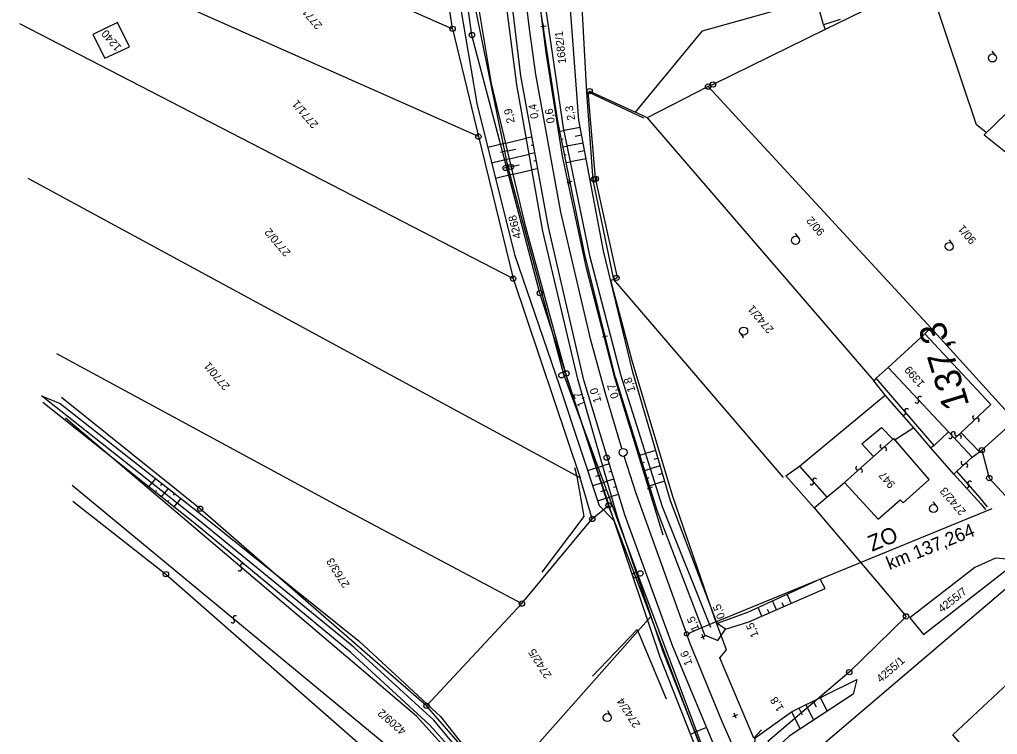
# Model space of a CAD drawing. Extents: x -658910 to -658078, y -1170373 to -1169331.
# Drawn here: x -658513.9 to -658330.6, y -1170257.1 to -1170123.2 of the extents above; entities that cross this region are included whole.
import ezdxf

# ---------------------------------------------------------------- set-up
doc = ezdxf.new("R2010")
doc.units = 0
for name, color, linetype in [('Vrstva 1', 7, 'Continuous'), ('Vrstva 10', 7, 'Continuous'), ('Vrstva 11', 7, 'Continuous'), ('Vrstva 12', 7, 'Continuous'), ('Vrstva 14', 7, 'Continuous'), ('Vrstva 26', 7, 'Continuous'), ('Vrstva 38', 7, 'Continuous'), ('Vrstva 39', 7, 'Continuous'), ('Vrstva 6', 7, 'Continuous'), ('Vrstva 7', 7, 'Continuous'), ('Vrstva 8', 7, 'Continuous'), ('Vrstva 9', 7, 'Continuous')]:
    doc.layers.add(name, color=color, linetype=linetype)

msp = doc.modelspace()

# ---------------------------------------------------------------- linework, layer by layer
at = {"layer": 'Vrstva 1'}
for p, q in [((-658429.152, -1170126.129), (-658429.052, -1170126.129)), ((-658407.12, -1170136.629), (-658407.02, -1170136.629)), ((-658406.295, -1170153.163), (-658406.195, -1170153.163)), ((-658406.295, -1170153.163), (-658406.195, -1170153.163)), ((-658405.941, -1170153.051), (-658405.841, -1170153.051)), ((-658402.07, -1170171.6), (-658401.97, -1170171.6)), ((-658416.448, -1170174.469), (-658416.348, -1170174.469)), ((-658403.55, -1170214.23), (-658403.45, -1170214.23)), ((-658403.55, -1170214.23), (-658403.45, -1170214.23)), ((-658347.82, -1170235.02), (-658347.72, -1170235.02)), ((-658358.46, -1170245.469), (-658358.36, -1170245.469))]:
    msp.add_line(p, q, dxfattribs=at)
for points in [[(-658403.5, -1170214.23), (-658416.398, -1170174.469), (-658429.102, -1170126.129), (-658434.469, -1170087.609), (-658436.09, -1170052.059), (-658435.91, -1170014.719), (-658434.91, -1170000.301)], [(-658407.281, -1170000.499), (-658408.153, -1170029.241), (-658409.34, -1170063.27), (-658409.781, -1170095.35), (-658409.699, -1170099.11), (-658407.621, -1170136.909), (-658406.442, -1170153.331), (-658402.571, -1170171.88), (-658370.821, -1170208.971)], [(-658370.27, -1170208.691), (-658365.012, -1170214.699), (-658352.621, -1170229.211), (-658347.77, -1170235.02), (-658358.41, -1170245.469), (-658373.641, -1170258.449), (-658367.441, -1170262.461), (-658359.102, -1170278.891), (-658351.488, -1170290.83), (-658344.789, -1170302.82), (-658321.379, -1170329.199), (-658330.469, -1170332.85)], [(-658330.469, -1170332.85), (-658356.398, -1170343.289), (-658366.66, -1170318.129), (-658369.211, -1170312.75), (-658376.602, -1170296.77), (-658379.789, -1170292.191), (-658390.738, -1170282.121), (-658389.18, -1170276.711), (-658384.27, -1170264.699), (-658395.621, -1170235.01), (-658403.5, -1170214.23)]]:
    msp.add_lwpolyline(points, dxfattribs=at)
for centre in [(-658429.102, -1170126.129), (-658407.07, -1170136.629), (-658406.245, -1170153.163), (-658406.245, -1170153.163), (-658405.891, -1170153.051), (-658402.02, -1170171.6), (-658416.398, -1170174.469), (-658403.5, -1170214.23), (-658403.5, -1170214.23), (-658347.77, -1170235.02), (-658358.41, -1170245.469)]:
    msp.add_circle(centre, 0.499, dxfattribs=at)
at = {"layer": 'Vrstva 10'}
for points in [[(-658398.979, -1170189.297), (-658404.442, -1170166.563), (-658409.088, -1170142.051), (-658411.131, -1170114.565), (-658412.045, -1170080.658), (-658411.524, -1170049.223), (-658409, -1170012.742), (-658406.097, -1169985.499), (-658398.397, -1169958.238), (-658397.23, -1169955.206)], [(-658417.872, -1169961.611), (-658420.49, -1169976.06), (-658420.7, -1169976.84), (-658423.094, -1169993.471), (-658426.642, -1170037.568), (-658427.061, -1170074.546), (-658424.838, -1170104.223), (-658420.758, -1170135.42), (-658415.909, -1170162.863), (-658409.329, -1170190.564)], [(-658402.315, -1170190.348), (-658407.653, -1170169.771), (-658412.172, -1170148.826), (-658415.215, -1170129.375), (-658417.727, -1170109.679), (-658419.363, -1170090.792), (-658420.432, -1170070.237), (-658420.644, -1170050.611), (-658420.516, -1170040.788), (-658419.395, -1170021.018), (-658418.485, -1170009.912), (-658416.352, -1169990.562), (-658415.125, -1169981.811), (-658411.561, -1169961.716)], [(-658411.065, -1170191.125), (-658419.009, -1170162.093), (-658425.437, -1170135.194), (-658430.311, -1170105.886), (-658434.217, -1170075.522), (-658434.962, -1170038.771), (-658431.942, -1169996.387), (-658433.406, -1169990.734), (-658432.798, -1169972.528), (-658431.022, -1169965.688)], [(-658408.116, -1170190.76), (-658414.795, -1170162.084), (-658419.971, -1170133.751), (-658423.753, -1170102.123), (-658425.468, -1170076.574), (-658425.385, -1170038.217), (-658422.281, -1169996.311), (-658419.933, -1169977.592), (-658415.95, -1169967.863)], [(-658434.217, -1170075.522), (-658435.579, -1170036.672), (-658434.69, -1170005.528), (-658435.667, -1169999.009), (-658437.119, -1170012.108), (-658437.881, -1170041.388), (-658436.997, -1170074.409), (-658433.517, -1170107.658), (-658428.206, -1170138.963), (-658421.128, -1170167.236), (-658412.684, -1170191.854)], [(-658402.19, -1170190.341), (-658407.996, -1170166.975), (-658412.991, -1170142.221), (-658416.888, -1170117.058), (-658418.194, -1170104.631), (-658416.97, -1170109.116), (-658415.845, -1170117.564), (-658412.003, -1170143.514), (-658407.102, -1170167.433), (-658401.285, -1170189.676)], [(-658412.605, -1170144.132), (-658411.906, -1170143.991)], [(-658408.831, -1170143.407), (-658411.906, -1170143.99)], [(-658422.766, -1170146.37), (-658426.149, -1170147.178)], [(-658422.766, -1170146.37), (-658418.922, -1170145.451)], [(-658417.868, -1170145.258), (-658418.922, -1170145.451)], [(-658412.309, -1170145.602), (-658412.027, -1170145.545)], [(-658408.272, -1170146.355), (-658411.303, -1170146.929)], [(-658408.552, -1170144.881), (-658409.773, -1170145.113)], [(-658422.417, -1170147.829), (-658423.764, -1170148.15)], [(-658422.417, -1170147.829), (-658420.915, -1170147.469)], [(-658417.329, -1170148.209), (-658418.4, -1170148.405)], [(-658417.599, -1170146.734), (-658418.024, -1170146.812)], [(-658412.012, -1170147.073), (-658411.303, -1170146.93)], [(-658407.993, -1170147.829), (-658409.197, -1170148.057)], [(-658422.069, -1170149.288), (-658425.421, -1170150.089)], [(-658422.069, -1170149.288), (-658418.399, -1170148.41)], [(-658417.06, -1170149.685), (-658417.491, -1170149.764)], [(-658411.715, -1170148.543), (-658411.43, -1170148.485)], [(-658411.419, -1170150.013), (-658410.701, -1170149.869)], [(-658407.714, -1170149.303), (-658410.701, -1170149.869)], [(-658421.72, -1170150.747), (-658423.055, -1170151.065)], [(-658421.72, -1170150.747), (-658420.287, -1170150.404)], [(-658421.372, -1170152.205), (-658417.876, -1170151.37)], [(-658416.79, -1170151.161), (-658417.878, -1170151.359)], [(-658421.372, -1170152.206), (-658424.692, -1170152.999)], [(-658393.284, -1170219.793), (-658402.315, -1170190.348)], [(-658402.19, -1170190.341), (-658394.439, -1170215.11), (-658385.518, -1170238.461), (-658383.011, -1170239.51), (-658381.573, -1170237.386), (-658383.18, -1170236.346), (-658391.879, -1170213.374), (-658398.979, -1170189.297)], [(-658401.285, -1170189.676), (-658393.487, -1170214.462), (-658384.399, -1170237.018)], [(-658412.684, -1170191.854), (-658405.295, -1170214.249), (-658402.529, -1170217.03)], [(-658411.065, -1170191.125), (-658402.529, -1170217.03), (-658393.894, -1170242.581), (-658385.65, -1170263.506), (-658396.929, -1170273.583), (-658403.806, -1170280.374), (-658404.2, -1170281.887), (-658401.638, -1170280.609), (-658395.562, -1170275.336), (-658385.028, -1170264.873), (-658381.412, -1170264.462)], [(-658385.028, -1170264.873), (-658384.852, -1170262.895), (-658393.339, -1170241.462), (-658401.853, -1170216.412), (-658409.267, -1170190.554)], [(-658382.68, -1170261.755), (-658391.453, -1170240.672), (-658400.481, -1170215.988), (-658408.116, -1170190.76)], [(-658427.834, -1170264.568), (-658436.224, -1170254.487), (-658451.234, -1170240.802), (-658480.159, -1170217.142), (-658509.779, -1170193.688), (-658506.26, -1170195.157), (-658479.671, -1170216.029), (-658450.164, -1170239.717), (-658435.016, -1170253.798), (-658426.918, -1170264.043), (-658428.464, -1170264.929), (-658436.985, -1170255.369), (-658451.79, -1170241.804), (-658480.719, -1170217.852), (-658509.548, -1170194.956)], [(-658397.652, -1170204.843), (-658396.615, -1170204.519)], [(-658394.66, -1170203.941), (-658396.615, -1170204.518)], [(-658405.77, -1170207.193), (-658404.606, -1170206.81)], [(-658403.371, -1170206.44), (-658404.605, -1170206.813)], [(-658397.204, -1170206.275), (-658396.788, -1170206.145)], [(-658393.812, -1170206.819), (-658395.715, -1170207.38)], [(-658394.236, -1170205.38), (-658395.008, -1170205.607)], [(-658405.771, -1170207.193), (-658407.441, -1170207.744)], [(-658405.301, -1170208.618), (-658405.969, -1170208.838)], [(-658405.301, -1170208.618), (-658404.857, -1170208.472)], [(-658402.936, -1170207.875), (-658403.438, -1170208.028)], [(-658396.756, -1170207.707), (-658395.715, -1170207.38)], [(-658393.387, -1170208.257), (-658394.138, -1170208.479)], [(-658489.628, -1170210.776), (-658489.076, -1170210.081)], [(-658488.379, -1170209.193), (-658489.076, -1170210.081)], [(-658487.2, -1170210.119), (-658487.48, -1170210.476)], [(-658404.832, -1170210.042), (-658406.501, -1170210.592)], [(-658404.832, -1170210.042), (-658403.778, -1170209.695)], [(-658402.501, -1170209.312), (-658403.778, -1170209.698)], [(-658396.308, -1170209.138), (-658395.891, -1170209.007)], [(-658395.86, -1170210.569), (-658394.814, -1170210.242)], [(-658392.963, -1170209.696), (-658394.814, -1170210.242)], [(-658488.454, -1170211.709), (-658488.232, -1170211.43)], [(-658487.279, -1170212.642), (-658486.724, -1170211.943)], [(-658486.02, -1170211.045), (-658486.724, -1170211.943)], [(-658484.84, -1170211.972), (-658485.123, -1170212.333)], [(-658404.362, -1170211.467), (-658405.03, -1170211.687)], [(-658404.362, -1170211.467), (-658403.963, -1170211.336)], [(-658401.632, -1170212.183), (-658402.951, -1170212.582)], [(-658402.067, -1170210.747), (-658402.586, -1170210.904)], [(-658486.104, -1170213.575), (-658485.882, -1170213.294)], [(-658484.93, -1170214.507), (-658484.372, -1170213.805)], [(-658483.66, -1170212.897), (-658484.372, -1170213.805)], [(-658403.893, -1170212.892), (-658405.561, -1170213.441)], [(-658403.893, -1170212.892), (-658402.951, -1170212.582)], [(-658381.573, -1170237.386), (-658377.211, -1170236.054), (-658362.918, -1170229.77), (-658363.874, -1170228.032), (-658377.506, -1170234.284), (-658383.18, -1170236.346)], [(-658372.041, -1170233.781), (-658372.774, -1170232.114)], [(-658370.668, -1170233.177), (-658370.965, -1170232.501)], [(-658369.295, -1170232.573), (-658370.047, -1170230.863)], [(-658374.787, -1170234.988), (-658375.501, -1170233.365)], [(-658373.414, -1170234.384), (-658373.703, -1170233.726)], [(-658376.215, -1170261.644), (-658376.011, -1170257.794), (-658369.212, -1170252.874), (-658357.015, -1170246.85), (-658357.668, -1170249.617), (-658369.7, -1170257.467), (-658372.946, -1170260.508)], [(-658365.177, -1170250.881), (-658364.634, -1170251.981)], [(-658363.832, -1170250.217), (-658362.554, -1170252.805)], [(-658367.867, -1170252.209), (-658367.26, -1170253.438)], [(-658366.522, -1170251.545), (-658365.085, -1170254.456)], [(-658369.212, -1170252.874), (-658367.615, -1170256.107)], [(-658385.149, -1170255.822), (-658387.299, -1170256.716)], [(-658388.187, -1170257.067), (-658387.298, -1170256.717)]]:
    msp.add_lwpolyline(points, dxfattribs=at)
at = {"layer": 'Vrstva 12'}
for p, q in [((-658416.194, -1170124.502), (-658415.203, -1170124.361)), ((-658415.628, -1170124.927), (-658415.769, -1170123.936)), ((-658411.293, -1170153.71), (-658410.318, -1170153.487)), ((-658410.694, -1170154.086), (-658410.917, -1170153.111)), ((-658404.665, -1170182.66), (-658403.69, -1170182.437)), ((-658404.066, -1170183.036), (-658404.289, -1170182.061)), ((-658395.646, -1170211.469), (-658395.985, -1170210.528)), ((-658395.345, -1170210.829), (-658396.286, -1170211.168)), ((-658385.304, -1170238.687), (-658386.231, -1170239.062)), ((-658385.58, -1170239.338), (-658385.955, -1170238.411)), ((-658379.347, -1170253.435), (-658380.262, -1170253.838)), ((-658379.603, -1170254.094), (-658380.006, -1170253.179))]:
    msp.add_line(p, q, dxfattribs=at)
for points in [[(-658399.067, -1170187.176), (-658403.097, -1170172.101), (-658401.841, -1170171.547), (-658405.936, -1170152.959), (-658407.353, -1170136.782), (-658396.958, -1170141.634)], [(-658399.067, -1170187.176), (-658403.097, -1170172.101), (-658401.841, -1170171.547), (-658405.936, -1170152.959), (-658407.353, -1170136.782), (-658396.958, -1170141.634)], [(-658374.854, -1170256.244), (-658376.266, -1170257.857), (-658382.638, -1170242.795), (-658381.434, -1170241.263), (-658383.587, -1170235.421), (-658391.447, -1170212.589), (-658399.067, -1170187.176)], [(-658374.854, -1170256.244), (-658376.266, -1170257.857), (-658382.638, -1170242.795), (-658381.434, -1170241.263), (-658383.587, -1170235.421), (-658391.447, -1170212.589), (-658399.067, -1170187.176)], [(-658409.885, -1170207.127), (-658409.448, -1170208.785), (-658408.134, -1170216.333), (-658416.024, -1170226.737)], [(-658409.885, -1170207.127), (-658409.448, -1170208.785), (-658408.134, -1170216.333), (-658416.024, -1170226.737)], [(-658406.538, -1170246.188), (-658398.144, -1170237.495), (-658392.744, -1170250.489)], [(-658406.538, -1170246.188), (-658398.144, -1170237.495), (-658392.744, -1170250.489)]]:
    msp.add_lwpolyline(points, dxfattribs=at)
at = {"layer": 'Vrstva 14'}
msp.add_circle((-658403.86, -1170205.272), 0.5, dxfattribs=at)
at = {"layer": 'Vrstva 26'}
for points in [[(-658422.321, -1170150.908), (-658429.464, -1170116.165)], [(-658411.874, -1170189.684), (-658422.321, -1170150.908)], [(-658370.027, -1170300), (-658377.149, -1170282.049), (-658386.214, -1170258.657), (-658398.024, -1170227.132), (-658411.874, -1170189.684)]]:
    msp.add_lwpolyline(points, dxfattribs=at)
for centre in [(-658422.81, -1170151.008), (-658421.831, -1170150.807), (-658412.342, -1170189.857), (-658411.405, -1170189.51), (-658398.492, -1170227.307), (-658397.555, -1170226.956)]:
    msp.add_circle(centre, 0.5, dxfattribs=at)
at = {"layer": 'Vrstva 38'}
msp.add_lwpolyline([(-658388.616, -1170238.202), (-658386.485, -1170237.314), (-658331.614, -1170214.793)], dxfattribs=at)
msp.add_circle((-658388.892, -1170238.29), 0.4, dxfattribs=at)
at = {"layer": 'Vrstva 6'}
for points in [[(-658404.069, -1170193.255), (-658406.802, -1170183.303), (-658412.437, -1170159.296), (-658417.118, -1170133.524), (-658418.339, -1170124.958), (-658420.433, -1170107.363)], [(-658401, -1170203.584), (-658404.069, -1170193.255)], [(-658388.156, -1170240.29), (-658398.345, -1170211.986), (-658400.56, -1170205.015)], [(-658363.328, -1170296.271), (-658369.128, -1170283.84), (-658375.834, -1170269.208), (-658382.293, -1170254.576), (-658388.156, -1170240.29)]]:
    msp.add_lwpolyline(points, dxfattribs=at)
msp.add_circle((-658400.788, -1170204.296), 0.75, dxfattribs=at)
at = {"layer": 'Vrstva 8'}
for p, q in [((-658432.78, -1170124.961), (-658432.68, -1170124.961)), ((-658432.78, -1170124.961), (-658432.68, -1170124.961)), ((-658383.991, -1170135.379), (-658383.891, -1170135.379)), ((-658384.909, -1170135.77), (-658384.809, -1170135.77)), ((-658384.909, -1170135.77), (-658384.809, -1170135.77)), ((-658427.948, -1170145.15), (-658427.848, -1170145.15)), ((-658427.948, -1170145.15), (-658427.848, -1170145.15)), ((-658403, -1170155), (-658403, -1170155)), ((-658421.441, -1170171.75), (-658421.341, -1170171.75)), ((-658421.441, -1170171.75), (-658421.341, -1170171.75)), ((-658337.48, -1170200.6), (-658337.48, -1170200.6)), ((-658334.012, -1170204.199), (-658334.012, -1170204.199)), ((-658333.609, -1170203.879), (-658333.509, -1170203.879)), ((-658333.609, -1170203.879), (-658333.509, -1170203.879)), ((-658332.222, -1170209.1), (-658332.122, -1170209.1)), ((-658480.081, -1170214.85), (-658479.981, -1170214.85)), ((-658406.62, -1170216.76), (-658406.52, -1170216.76)), ((-658406.62, -1170216.76), (-658406.52, -1170216.76)), ((-658486.499, -1170227.109), (-658486.399, -1170227.109)), ((-658419.8, -1170232.629), (-658419.7, -1170232.629)), ((-658419.8, -1170232.629), (-658419.7, -1170232.629)), ((-658437.679, -1170251.781), (-658437.579, -1170251.781)), ((-658437.679, -1170251.781), (-658437.579, -1170251.781)), ((-658437.679, -1170251.781), (-658437.579, -1170251.781))]:
    msp.add_line(p, q, dxfattribs=at)
for points in [[(-658483.512, -1170102.52), (-658432.73, -1170124.961), (-658438.469, -1170085.941)], [(-658432.73, -1170124.961), (-658427.898, -1170145.15), (-658491.949, -1170116.66), (-658492.5, -1170116.51), (-658494.488, -1170117.301), (-658497.551, -1170107.359), (-658486.379, -1170104.051), (-658483.352, -1170113.789), (-658492.5, -1170116.51)], [(-658343.781, -1170115.711), (-658362.941, -1170125.1), (-658383.941, -1170135.379), (-658384.859, -1170135.77), (-658396.301, -1170141.629), (-658398.469, -1170140.59), (-658385.91, -1170125.309), (-658364.672, -1170119.32)], [(-658332.82, -1170144.281), (-658334.559, -1170142.949), (-658342.941, -1170117.961)], [(-658360.109, -1170123.199), (-658363.262, -1170124.211), (-658364.109, -1170121.039)], [(-658513.879, -1170123.961), (-658421.391, -1170171.75), (-658408.84, -1170209.09)], [(-658363.262, -1170124.211), (-658362.941, -1170125.1)], [(-658318.371, -1170130.531), (-658333.141, -1170144.789), (-658329.059, -1170148.059), (-658326.859, -1170149.789), (-658324.578, -1170151.859), (-658326, -1170153.76), (-658322.172, -1170156.539), (-658312.941, -1170163.66), (-658311.129, -1170161.539), (-658309.211, -1170162.891), (-658303.559, -1170155.359)], [(-658407.07, -1170136.629), (-658398.469, -1170140.59)], [(-658384.859, -1170135.77), (-658343.121, -1170180.961), (-658327.41, -1170198.301), (-658333.559, -1170203.879), (-658332.172, -1170209.1), (-658327.551, -1170214.141), (-658321.59, -1170219.16), (-658320.828, -1170219.93), (-658325.852, -1170225.359), (-658326.648, -1170224.5), (-658330.98, -1170224.109), (-658334.898, -1170225.871), (-658347.059, -1170235.289), (-658344.5, -1170238.391), (-658326.648, -1170224.5)], [(-658396.301, -1170141.629), (-658353.781, -1170190.871)], [(-658427.898, -1170145.15), (-658421.391, -1170171.75)], [(-658506.93, -1170185.75), (-658454.141, -1170214.391), (-658419.75, -1170232.629), (-658406.57, -1170216.76), (-658408.84, -1170209.09), (-658512.289, -1170153.02)], [(-658344.262, -1170182.09), (-658343.121, -1170180.961)], [(-658339.82, -1170200.449), (-658351.121, -1170188.41), (-658344.262, -1170182.09), (-658331.852, -1170195.35), (-658338.602, -1170201.67)], [(-658353.379, -1170190.391), (-658351.121, -1170188.41)], [(-658338.281, -1170207.83), (-658335.379, -1170205.191), (-658339.82, -1170200.449), (-658342.469, -1170203.031), (-658353.379, -1170190.391), (-658353.781, -1170190.871)], [(-658370.27, -1170208.691), (-658367.711, -1170206.859), (-658351.66, -1170193.57), (-658353.781, -1170190.871)], [(-658367.441, -1170262.461), (-658305.121, -1170209.41), (-658290.129, -1170191.49)], [(-658437.629, -1170251.781), (-658480.031, -1170214.85), (-658506.031, -1170194.039)], [(-658338.809, -1170208.371), (-658343.102, -1170203.461), (-658346.309, -1170199.711), (-658351.66, -1170193.57)], [(-658439.469, -1170253.74), (-658505.27, -1170197.9)], [(-658365.012, -1170214.699), (-658362.602, -1170212.67), (-658359.27, -1170209.91), (-658353.012, -1170216.809), (-658348.84, -1170213.211), (-658348.289, -1170213.74), (-658343.43, -1170209.35), (-658350.031, -1170201.67), (-658353.84, -1170205.07), (-658356.039, -1170202.691), (-658352.352, -1170199.609), (-658350.238, -1170201.809)], [(-658346.309, -1170199.711), (-658349.801, -1170201.949)], [(-658334.012, -1170204.199), (-658337.48, -1170200.6)], [(-658342.469, -1170203.031), (-658343.102, -1170203.461)], [(-658353.84, -1170205.07), (-658359.27, -1170209.91)], [(-658335.379, -1170205.191), (-658333.559, -1170203.879)], [(-658367.711, -1170206.859), (-658362.602, -1170212.67)], [(-658332.531, -1170214.466), (-658333.922, -1170212.77), (-658338.281, -1170207.83), (-658338.809, -1170208.371), (-658333.75, -1170213.941), (-658332.905, -1170215.021)], [(-658443.422, -1170260.6), (-658504.02, -1170210.5)], [(-658503.871, -1170213.42), (-658486.449, -1170227.109), (-658446.422, -1170262.219)], [(-658406.57, -1170216.76), (-658403.5, -1170214.23)], [(-658419.75, -1170232.629), (-658437.629, -1170251.781)], [(-658407.27, -1170321.32), (-658411.031, -1170302.51), (-658413.109, -1170292.49), (-658415.109, -1170286.801), (-658420.691, -1170271.91), (-658424.129, -1170267.281), (-658395.621, -1170235.01)], [(-658324.686, -1170273.482), (-658339.031, -1170257.199), (-658327.789, -1170246.691)], [(-658424.129, -1170267.281), (-658437.629, -1170251.781)], [(-658411.93, -1170371.551), (-658412.051, -1170358.6), (-658411.02, -1170322.441), (-658416.07, -1170292.65), (-658423.141, -1170271.82), (-658439.469, -1170253.74)]]:
    msp.add_lwpolyline(points, dxfattribs=at)
msp.add_lwpolyline([(-658497.93, -1170130.461), (-658493.25, -1170128.33), (-658495.551, -1170123.77), (-658500.172, -1170126.039)], close=True, dxfattribs=at)
for centre in [(-658432.73, -1170124.961), (-658432.73, -1170124.961), (-658384.859, -1170135.77), (-658384.859, -1170135.77), (-658383.941, -1170135.379), (-658427.898, -1170145.15), (-658427.898, -1170145.15), (-658421.391, -1170171.75), (-658421.391, -1170171.75), (-658333.559, -1170203.879), (-658333.559, -1170203.879), (-658332.172, -1170209.1), (-658480.031, -1170214.85), (-658406.57, -1170216.76), (-658406.57, -1170216.76), (-658486.449, -1170227.109), (-658419.75, -1170232.629), (-658419.75, -1170232.629), (-658437.629, -1170251.781), (-658437.629, -1170251.781), (-658437.629, -1170251.781)]:
    msp.add_circle(centre, 0.499, dxfattribs=at)
for centre, radius, start, end in [((-658345.194, -1170194.172), 0.377, 35.54775, 223.21097), ((-658345.746, -1170194.684), 0.376, 216.22379, 42.53493), ((-658348.209, -1170196.953), 0.376, 213.81909, 40.13022), ((-658347.636, -1170196.464), 0.377, 33.14305, 220.80626), ((-658334.925, -1170197.69), 0.376, 126.01713, 312.32826), ((-658334.415, -1170198.244), 0.377, 305.34109, 133.0043), ((-658339.48, -1170201.321), 0.376, 217.93866, 44.24979), ((-658338.944, -1170200.793), 0.377, 37.26262, 224.92583), ((-658338.296, -1170200.854), 0.376, 126.80265, 313.11378), ((-658337.778, -1170201.4), 0.377, 306.12661, 133.78982), ((-658352.288, -1170203.158), 0.376, 125.14755, 311.45869), ((-658351.786, -1170203.72), 0.377, 304.47151, 132.13473), ((-658356.806, -1170207.206), 0.376, 124.75457, 311.0657), ((-658337.077, -1170206.228), 0.376, 125.30206, 311.61319), ((-658336.574, -1170206.788), 0.377, 304.62601, 132.28923), ((-658356.308, -1170207.771), 0.377, 304.07853, 131.74174), ((-658365.442, -1170210.008), 0.377, 213.65174, 41.31496), ((-658364.874, -1170209.514), 0.376, 34.32778, 220.63892), ((-658336.384, -1170210.55), 0.377, 213.78467, 41.44788), ((-658335.816, -1170210.055), 0.376, 34.46071, 220.77184), ((-658472.124, -1170225.535), 0.376, 42.71187, 229.02301), ((-658472.614, -1170226.107), 0.377, 222.03583, 49.69905), ((-658473.959, -1170235.841), 0.377, 222.76864, 50.43186), ((-658473.475, -1170235.263), 0.376, 43.44469, 229.75582)]:
    msp.add_arc(centre, radius, start, end, dxfattribs=at)
at = {"layer": 'Vrstva 9'}
for p, q in [((-658330.999, -1170129.922), (-658331.655, -1170129.167)), ((-658367.878, -1170164.134), (-658368.463, -1170163.323)), ((-658339.059, -1170165.28), (-658339.644, -1170164.469)), ((-658378.801, -1170182.031), (-658378.206, -1170182.835)), ((-658342.056, -1170214.334), (-658342.711, -1170213.578)), ((-658403.12, -1170253.563), (-658403.658, -1170252.72))]:
    msp.add_line(p, q, dxfattribs=at)
for centre in [(-658331.566, -1170130.414), (-658368.487, -1170164.573), (-658339.668, -1170165.719), (-658378.197, -1170181.585), (-658342.624, -1170214.825), (-658403.753, -1170253.967)]:
    msp.add_circle(centre, 0.75, dxfattribs=at)

# ---------------------------------------------------------------- texts
at = {"layer": 'Vrstva 11'}
for s, rotation, p in [('1682/1', 96.23428, (-658411.45, -1170131.4)), ('0,4', 99.63963, (-658416.606, -1170141.671)), ('2,9', 103.441, (-658421.068, -1170142.457)), ('0,6', 99.0823, (-658413.571, -1170142.53)), ('2,3', 100.13506, (-658409.744, -1170141.977)), ('1,8', 107.65029, (-658398.451, -1170192.747)), ('1,0', 108.00825, (-658404.81, -1170194.712)), ('0,7', 107.37731, (-658401.566, -1170193.951)), ('1,7', 111.25192, (-658407.764, -1170195.431)), ('0,5', 111.51783, (-658381.632, -1170235.152)), ('1,5', 112.35461, (-658386.449, -1170237.427)), ('1,5', 113.73003, (-658375.337, -1170238.599)), ('1,6', 110.48256, (-658387.772, -1170243.907)), ('1,8', 123.12255, (-658370.575, -1170252.247))]:
    msp.add_text(s, height=1.5, rotation=rotation, dxfattribs=at).set_placement(p)
at = {"layer": 'Vrstva 39'}
for s, height, rotation, p in [('km 137,264', 2.5, 21.91546, (-658350.867, -1170226.362)), ('ZO', 3, 22.31447, (-658354.15, -1170222.921))]:
    msp.add_text(s, height=height, rotation=rotation, dxfattribs=at).set_placement(p)
at = {"layer": 'Vrstva 7'}
msp.add_text('137,3', height=4.999, rotation=106.99257, dxfattribs=at).set_placement((-658335.876, -1170195.44))
at = {"layer": 'Vrstva 9'}
for s, rotation, p in [('2771/2', 130.49568, (-658457.05, -1170124.264)), ('1240', 130.49568, (-658494.66, -1170128.366)), ('2771/1', 130.49568, (-658457.813, -1170142.815)), ('4268', 103.74876, (-658419.819, -1170164.07)), ('90/2', 130.49568, (-658362.902, -1170162.951)), ('2770/2', 130.49568, (-658462.983, -1170166.824)), ('90/1', 130.49568, (-658334.5, -1170164.509)), ('2742/1', 130.49568, (-658372.47, -1170181.225)), ('2770/1', 130.49568, (-658474.382, -1170191.863)), ('1399', 130.49568, (-658344.168, -1170191.356)), ('947', 130.49568, (-658349.696, -1170210.251)), ('2742/3', 130.49568, (-658336.436, -1170215.326)), ('2763/3', 122.51061, (-658451.939, -1170229.076)), ('4255/7', 37.87325, (-658341.051, -1170234.41)), ('2742/5', 122.51061, (-658414.102, -1170246.085)), ('4255/1', 40.62158, (-658352.523, -1170247.509)), ('2742/4', 122.51061, (-658397.491, -1170255.286)), ('4209/2', 139.00941, (-658441.311, -1170256.274))]:
    msp.add_text(s, height=1.5, rotation=rotation, dxfattribs=at).set_placement(p)

doc.saveas('drawing.dxf')
